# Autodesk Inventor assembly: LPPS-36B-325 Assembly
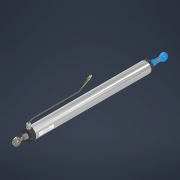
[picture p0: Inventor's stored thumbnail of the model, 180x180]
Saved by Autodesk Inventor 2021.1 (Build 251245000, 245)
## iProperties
Created: 2020-09
Part Number: LPPS-36B-325 Assembly
Document SubType Name: Assembly
Designer: J. Nielson
Author: J. Nielson
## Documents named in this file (3)
- C:\Users\Justin\Documents\CAD\The Sensor Connection\LPPS\LPPS-36B Series\3D\LPPS 36B-325\LPPS-36B-325 Assembly.iam
- C:\Users\Justin\Documents\CAD\The Sensor Connection\LPPS\LPPS-36B Series\3D\LPPS 36B-325\LPPS 36B-325_Shrinkwrap.ipt
- C:\Users\Justin\Documents\CAD\The Sensor Connection\LPPS\LPPS-36B Series\3D\LPPS 36B-325\LPPS 36B-325_Shaft_Shrinkwrap.ipt
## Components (2 placed, 2 different names)
1. LPPS 36B-325_Shrinkwrap:1 — Mate:1, Angle:1, Cylindrical:1
2. LPPS 36B-325_Shaft_Shrinkwrap:1 — Mate:1, Angle:1, Cylindrical:1
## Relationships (3: Mate 1, Angle 1, CylindricalJoint 1)
- Mate:1: LPPS 36B-325_Shrinkwrap:1 ↔ LPPS 36B-325_Shaft_Shrinkwrap:1
- Angle:1: LPPS 36B-325_Shrinkwrap:1 ↔ LPPS 36B-325_Shaft_Shrinkwrap:1
- Cylindrical:1: LPPS 36B-325_Shrinkwrap:1 ↔ LPPS 36B-325_Shaft_Shrinkwrap:1
